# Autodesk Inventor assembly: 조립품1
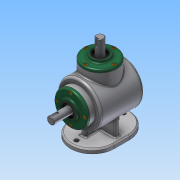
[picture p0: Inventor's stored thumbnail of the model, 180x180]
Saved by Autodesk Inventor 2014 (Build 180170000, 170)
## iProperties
Created: 2016-04
Part Number: 조립품1
Document SubType Name: Assembly
Designer: 601-
Author: 601-
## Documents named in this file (14)
- C:\Users\601-\Desktop\조립품1.iam
- C:\Users\601-\Desktop\본체.ipt
- C:\Users\601-\Desktop\460408v1014\메인 축.ipt
- 메인 축.ipt
- C:\Users\601-\Desktop\460408v1014\메인 베벨기어.ipt
- C:\Users\601-\Desktop\460408v1014\키 5x5.ipt
- C:\Users\601-\Desktop\460408v1014\베어링 6203.ipt
- C:\Users\601-\Desktop\460408v1014\커버.ipt
- C:\Users\601-\Desktop\460408v1014\오일실 17 32 8.ipt
- C:\Users\601-\Desktop\460408v1014\M4.ipt
- C:\Users\601-\Desktop\460408v1014\서브 축.ipt
- 서브 축.ipt
- C:\Users\601-\Desktop\460408v1014\키 4x4.ipt
- C:\Users\601-\Desktop\460408v1014\서브 베벨기어.ipt
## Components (8 placed, 1 different names)
1. M4:1
2. M4:2
3. M4:3
4. M4:4
5. M4:5
6. M4:6
7. M4:7
8. M4:8
